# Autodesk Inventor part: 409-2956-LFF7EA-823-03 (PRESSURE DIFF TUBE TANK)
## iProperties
Created: 2010-09
Part Number: 409-2956-LFF7EA-823-03 (PRESSURE DIFF TUBE TANK)
Material: 3/8" OD TUBE - SS
Document SubType Name: Modeling
Designer: S. Boerckel
Engineer: Steve Boerckel
Mass: 61.6007 g
Surface Area: 127.01 cm^2
Volume: 7.62385 cm^3
Density: 8.08 g/cm^3
Description: LOWE PRESSURE GAUGE TUBE
LGTH: 2.820 in
Author: S. Boerckel
Revision Number: 0
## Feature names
1. Sweep3
